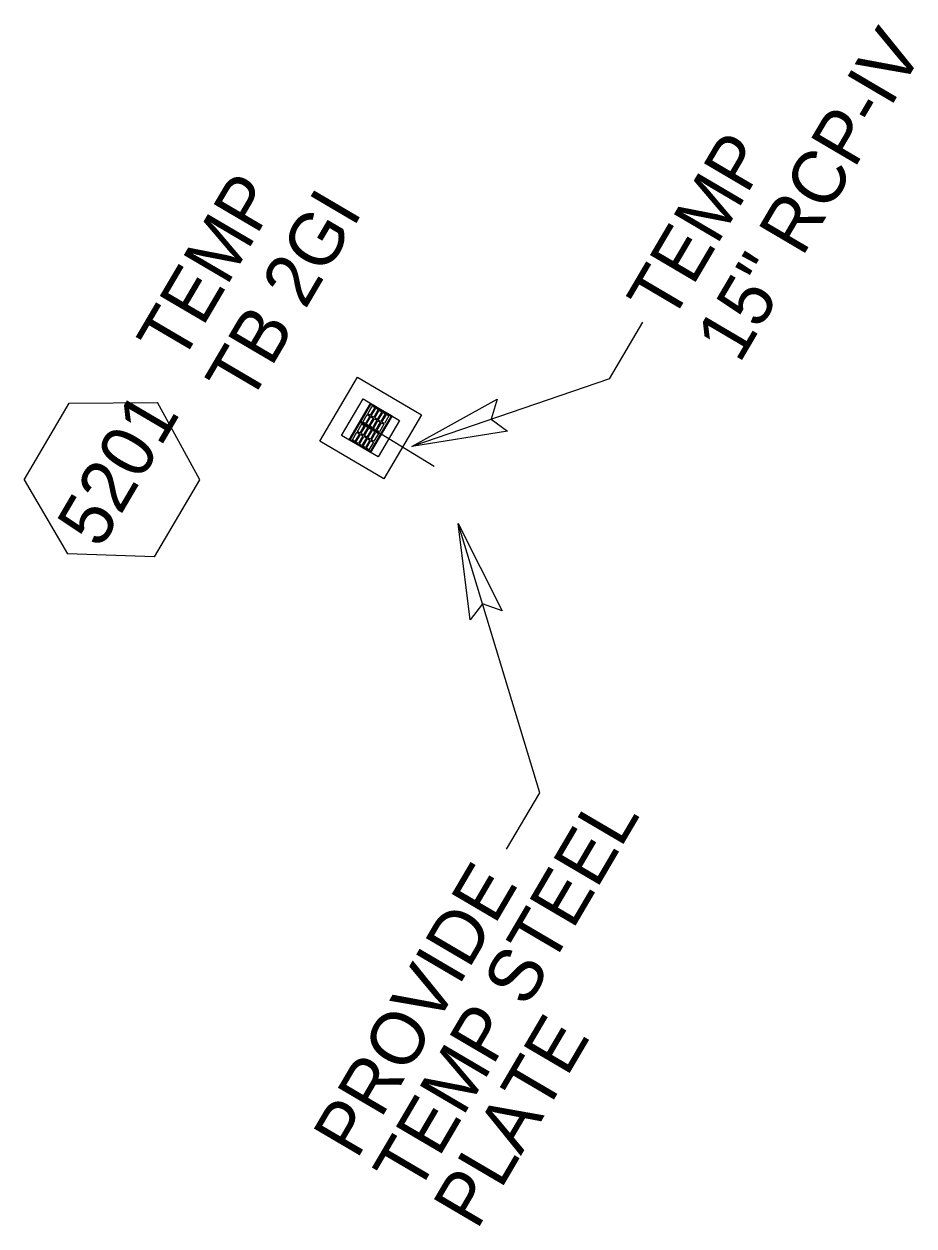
# Model space of a CAD drawing. Extents: x 2214419 to 2238519, y 983271 to 1015868.
# Drawn here: x 2232305.7 to 2232389.5, y 1005338.5 to 1005451.8 of the extents above; entities that cross this region are included whole.
import ezdxf

# ---------------------------------------------------------------- set-up
doc = ezdxf.new("R2010")
doc.units = 0
for name, color, linetype in [('Prop Drainage Structure Box Number Symbol CELL', 7, 'Continuous'), ('Prop Drainage Structure Drop Inlet Grate 2 Wide Slots and Sag Grates 840 22 TB CELL', 7, 'Continuous'), ('Prop Drainage Structure Drop Inlet Grate 2 Wide Slots and Sag Grates 840 22 TB Label', 7, 'Continuous'), ('Prop Drainage Structure Pipe RCP 15in Class IV', 7, 'Continuous'), ('Prop Drainage Structure Pipe RCP 15in Class IV Label', 7, 'Continuous'), ('Prop Drainage Structure Plot Symbol 20 Scale', 7, 'Continuous'), ('Prop Drainage Structure Plot Symbol 50 Scale', 7, 'Continuous'), ('Prop Plan Preparation Drainage Notes Label', 7, 'Continuous')]:
    doc.layers.add(name, color=color, linetype=linetype)

msp = doc.modelspace()

# ---------------------------------------------------------------- linework, layer by layer
at = {"layer": 'Prop Drainage Structure Box Number Symbol CELL'}
for p, q in [((2232305.7, 1005408.82), (2232309.95, 1005416.06)), ((2232309.95, 1005416.06), (2232318.27, 1005416.12)), ((2232322.26, 1005408.83), (2232318.27, 1005416.12)), ((2232305.7, 1005408.82), (2232309.8, 1005401.86)), ((2232318, 1005401.59), (2232322.26, 1005408.83)), ((2232318, 1005401.59), (2232309.8, 1005401.86))]:
    msp.add_line(p, q, dxfattribs=at)
at = {"layer": 'Prop Drainage Structure Drop Inlet Grate 2 Wide Slots and Sag Grates 840 22 TB CELL'}
for p, q in [((2232339.36, 1005415.44), (2232339.36, 1005415.44)), ((2232337.34, 1005414.31), (2232337.34, 1005414.31)), ((2232338.35, 1005413.72), (2232338.35, 1005413.72)), ((2232339.35, 1005413.13), (2232339.35, 1005413.13)), ((2232337.33, 1005412), (2232337.33, 1005412))]:
    msp.add_line(p, q, dxfattribs=at)
for points in [[(2232340.37, 1005414.85), (2232338.34, 1005411.4), (2232336.33, 1005412.59), (2232338.35, 1005416.03), (2232340.37, 1005414.85)], [(2232340.28, 1005414.83), (2232338.32, 1005411.49), (2232336.41, 1005412.61), (2232338.38, 1005415.95), (2232340.28, 1005414.83), (2232340.28, 1005414.83)], [(2232340.27, 1005414.83), (2232339.29, 1005413.17), (2232337.41, 1005414.28), (2232338.38, 1005415.94), (2232340.27, 1005414.83)], [(2232338.27, 1005414.84), (2232337.85, 1005414.12), (2232337.61, 1005414.26), (2232338.03, 1005414.98), (2232338.27, 1005414.84)], [(2232338.73, 1005415.63), (2232338.31, 1005414.91), (2232338.08, 1005415.05), (2232338.5, 1005415.77), (2232338.73, 1005415.63)], [(2232339.06, 1005415.44), (2232338.64, 1005414.72), (2232338.41, 1005414.85), (2232338.83, 1005415.57), (2232339.06, 1005415.44)], [(2232339.4, 1005415.24), (2232338.97, 1005414.52), (2232338.74, 1005414.66), (2232339.16, 1005415.38), (2232339.4, 1005415.24)], [(2232339.73, 1005415.04), (2232339.31, 1005414.33), (2232339.07, 1005414.46), (2232339.5, 1005415.18), (2232339.73, 1005415.04)], [(2232340.06, 1005414.85), (2232339.64, 1005414.13), (2232339.41, 1005414.27), (2232339.83, 1005414.99), (2232340.06, 1005414.85)], [(2232339.28, 1005413.16), (2232338.31, 1005411.5), (2232336.43, 1005412.61), (2232337.4, 1005414.26), (2232339.28, 1005413.16)], [(2232337.75, 1005413.96), (2232337.33, 1005413.24), (2232337.1, 1005413.38), (2232337.52, 1005414.1), (2232337.75, 1005413.96)], [(2232338.08, 1005413.77), (2232337.66, 1005413.05), (2232337.43, 1005413.18), (2232337.85, 1005413.9), (2232338.08, 1005413.77)], [(2232338.6, 1005414.65), (2232338.18, 1005413.93), (2232337.94, 1005414.06), (2232338.37, 1005414.78), (2232338.6, 1005414.65)], [(2232338.93, 1005414.45), (2232338.51, 1005413.73), (2232338.28, 1005413.87), (2232338.7, 1005414.59), (2232338.93, 1005414.45)], [(2232339.26, 1005414.25), (2232338.84, 1005413.54), (2232338.61, 1005413.67), (2232339.03, 1005414.39), (2232339.26, 1005414.25)], [(2232339.6, 1005414.06), (2232339.17, 1005413.34), (2232338.94, 1005413.48), (2232339.36, 1005414.2), (2232339.6, 1005414.06)], [(2232337.29, 1005413.17), (2232336.86, 1005412.45), (2232336.63, 1005412.59), (2232337.05, 1005413.31), (2232337.29, 1005413.17)], [(2232337.62, 1005412.98), (2232337.2, 1005412.26), (2232336.96, 1005412.39), (2232337.39, 1005413.11), (2232337.62, 1005412.98)], [(2232337.95, 1005412.78), (2232337.53, 1005412.06), (2232337.3, 1005412.2), (2232337.72, 1005412.92), (2232337.95, 1005412.78)], [(2232338.28, 1005412.58), (2232337.86, 1005411.87), (2232337.63, 1005412), (2232338.05, 1005412.72), (2232338.28, 1005412.58)], [(2232338.42, 1005413.57), (2232337.99, 1005412.85), (2232337.76, 1005412.99), (2232338.18, 1005413.71), (2232338.42, 1005413.57)], [(2232338.75, 1005413.37), (2232338.33, 1005412.66), (2232338.09, 1005412.79), (2232338.51, 1005413.51), (2232338.75, 1005413.37)], [(2232339.08, 1005413.18), (2232338.66, 1005412.46), (2232338.42, 1005412.6), (2232338.85, 1005413.32), (2232339.08, 1005413.18)], [(2232338.62, 1005412.39), (2232338.19, 1005411.67), (2232337.96, 1005411.81), (2232338.38, 1005412.53), (2232338.62, 1005412.39)]]:
    msp.add_lwpolyline(points, dxfattribs=at)
at = {"layer": 'Prop Drainage Structure Pipe RCP 15in Class IV'}
msp.add_line((2232344.33, 1005410.08), (2232339.35, 1005413.13), dxfattribs=at)
at = {"layer": 'Prop Drainage Structure Plot Symbol 20 Scale'}
msp.add_lwpolyline([(2232341.08, 1005414.43), (2232339.06, 1005410.98), (2232335.61, 1005413.01), (2232337.64, 1005416.46)], close=True, dxfattribs=at)
at = {"layer": 'Prop Drainage Structure Plot Symbol 50 Scale'}
msp.add_lwpolyline([(2232343.14, 1005414.96), (2232339.59, 1005408.93), (2232333.56, 1005412.48), (2232337.1, 1005418.51)], close=True, dxfattribs=at)
at = {"layer": 'Prop Plan Preparation Drainage Notes Label'}
for p, q in [((2232360.86, 1005418.35), (2232363.99, 1005423.67)), ((2232360.86, 1005418.35), (2232342.23, 1005411.98)), ((2232354.29, 1005379.34), (2232346.58, 1005404.7)), ((2232351.16, 1005374.02), (2232354.29, 1005379.34))]:
    msp.add_line(p, q, dxfattribs=at)
for points in [[(2232351.24, 1005413.42), (2232342.23, 1005411.98), (2232350.27, 1005416.42), (2232349.7, 1005414.54)], [(2232347.72, 1005395.64), (2232346.58, 1005404.7), (2232350.75, 1005396.5), (2232348.88, 1005397.14)]]:
    msp.add_lwpolyline(points, close=True, dxfattribs=at)

# ---------------------------------------------------------------- texts
at = {"layer": 'Prop Drainage Structure Box Number Symbol CELL'}
msp.add_text('5201', height=5, rotation=59.5518, dxfattribs=at).set_placement((2232312.89, 1005402.21))
at = {"layer": 'Prop Drainage Structure Drop Inlet Grate 2 Wide Slots and Sag Grates 840 22 TB Label'}
for s, p in [('TEMP', (2232320.45, 1005419.63)), ('TB 2GI', (2232326.91, 1005415.83))]:
    msp.add_text(s, height=5, rotation=59.5518, dxfattribs=at).set_placement(p)
at = {"layer": 'Prop Drainage Structure Pipe RCP 15in Class IV Label'}
for s, p in [('15" RCP-IV ', (2232373.08, 1005419.68)), ('TEMP', (2232366.62, 1005423.48))]:
    msp.add_text(s, height=5, rotation=59.5047, dxfattribs=at).set_placement(p)
at = {"layer": 'Prop Plan Preparation Drainage Notes Label'}
for s, p in [('TEMP STEEL', (2232342.7, 1005341.38)), ('PROVIDE', (2232337.04, 1005344.71)), ('PLATE', (2232348.35, 1005338.06))]:
    msp.add_text(s, height=5, rotation=59.566, dxfattribs=at).set_placement(p)

doc.saveas('drawing.dxf')
